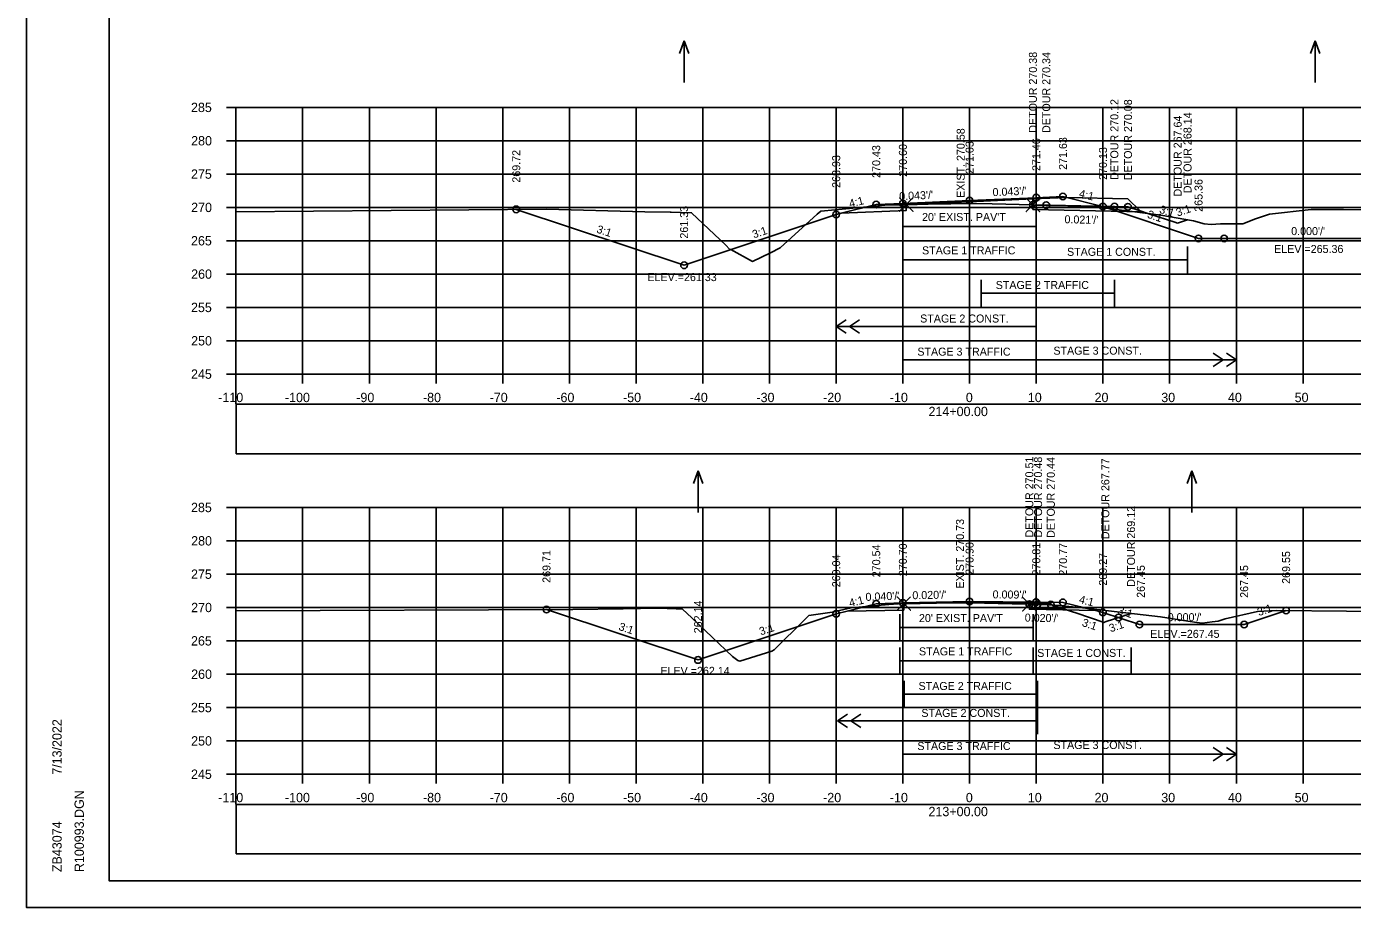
# Model space of a CAD drawing. Extents: x 4667 to 1632277, y -2100 to 724501.
# Drawn here: x 5635.8 to 5834.6, y -1750.4 to -1618.3 of the extents above; entities that cross this region are included whole.
import ezdxf

# ---------------------------------------------------------------- set-up
doc = ezdxf.new("R2010")
doc.units = 0
for name, color, linetype in [('R_Alt Surface', 7, 'Continuous'), ('R_Axis', 7, 'Continuous'), ('R_Axis Annot', 7, 'Continuous'), ('R_Border', 7, 'Continuous'), ('R_Detour', 7, 'Continuous'), ('R_Detour Annot', 7, 'Continuous'), ('R_Exist Surface', 7, 'Continuous'), ('R_Fin Surface', 7, 'Continuous'), ('R_Fin Surface Annot', 7, 'Continuous'), ('R_Grid', 7, 'Continuous'), ('R_No Plot', 7, 'Continuous'), ('R_Proposed CofA', 7, 'Continuous'), ('R_Temp Easement', 7, 'Continuous'), ('R_Water Annot', 7, 'Continuous'), ('T_Notes', 7, 'Continuous')]:
    doc.layers.add(name, color=color, linetype=linetype)

msp = doc.modelspace()

# ---------------------------------------------------------------- linework, layer by layer
at = {"layer": 'R_Alt Surface'}
for points in [[(5757.95, -1646.32), (5767.69, -1645.9), (5767.69, -1644.99), (5777.18, -1644.58), (5786.68, -1644.17), (5786.68, -1645.09), (5797.13, -1645.3)], [(5758.82, -1705.99), (5767.32, -1705.82), (5767.32, -1704.91), (5777.18, -1704.71), (5786.14, -1704.79), (5786.14, -1705.71), (5796.13, -1705.91)]]:
    msp.add_lwpolyline(points, dxfattribs=at)
at = {"layer": 'R_Axis'}
for p, q in [((5665.78, -1630.44), (5667.18, -1630.44)), ((5667.18, -1670.44), (5667.18, -1630.44)), ((5665.78, -1635.44), (5667.18, -1635.44)), ((5665.78, -1640.44), (5667.18, -1640.44)), ((5665.78, -1645.44), (5667.18, -1645.44)), ((5665.78, -1650.44), (5667.18, -1650.44)), ((5665.78, -1655.44), (5667.18, -1655.44)), ((5665.78, -1660.44), (5667.18, -1660.44)), ((5665.78, -1665.44), (5667.18, -1665.44)), ((5665.78, -1670.44), (5667.18, -1670.44)), ((5667.18, -1670.44), (5947.18, -1670.44)), ((5667.18, -1671.84), (5667.18, -1670.44)), ((5677.18, -1671.84), (5677.18, -1670.44)), ((5687.18, -1671.84), (5687.18, -1670.44)), ((5697.18, -1671.84), (5697.18, -1670.44)), ((5707.18, -1671.84), (5707.18, -1670.44)), ((5717.18, -1671.84), (5717.18, -1670.44)), ((5727.18, -1671.84), (5727.18, -1670.44)), ((5737.18, -1671.84), (5737.18, -1670.44)), ((5747.18, -1671.84), (5747.18, -1670.44)), ((5757.18, -1671.84), (5757.18, -1670.44)), ((5767.18, -1671.84), (5767.18, -1670.44)), ((5777.18, -1671.84), (5777.18, -1670.44)), ((5787.18, -1671.84), (5787.18, -1670.44)), ((5797.18, -1671.84), (5797.18, -1670.44)), ((5807.18, -1671.84), (5807.18, -1670.44)), ((5817.18, -1671.84), (5817.18, -1670.44)), ((5827.18, -1671.84), (5827.18, -1670.44)), ((5665.78, -1690.44), (5667.18, -1690.44)), ((5667.18, -1730.44), (5667.18, -1690.44)), ((5665.78, -1695.44), (5667.18, -1695.44)), ((5665.78, -1700.44), (5667.18, -1700.44)), ((5665.78, -1705.44), (5667.18, -1705.44)), ((5665.78, -1710.44), (5667.18, -1710.44)), ((5665.78, -1715.44), (5667.18, -1715.44)), ((5665.78, -1720.44), (5667.18, -1720.44)), ((5665.78, -1725.44), (5667.18, -1725.44)), ((5665.78, -1730.44), (5667.18, -1730.44)), ((5667.18, -1730.44), (5947.18, -1730.44)), ((5667.18, -1731.84), (5667.18, -1730.44)), ((5677.18, -1731.84), (5677.18, -1730.44)), ((5687.18, -1731.84), (5687.18, -1730.44)), ((5697.18, -1731.84), (5697.18, -1730.44)), ((5707.18, -1731.84), (5707.18, -1730.44)), ((5717.18, -1731.84), (5717.18, -1730.44)), ((5727.18, -1731.84), (5727.18, -1730.44)), ((5737.18, -1731.84), (5737.18, -1730.44)), ((5747.18, -1731.84), (5747.18, -1730.44)), ((5757.18, -1731.84), (5757.18, -1730.44)), ((5767.18, -1731.84), (5767.18, -1730.44)), ((5777.18, -1731.84), (5777.18, -1730.44)), ((5787.18, -1731.84), (5787.18, -1730.44)), ((5797.18, -1731.84), (5797.18, -1730.44)), ((5807.18, -1731.84), (5807.18, -1730.44)), ((5817.18, -1731.84), (5817.18, -1730.44)), ((5827.18, -1731.84), (5827.18, -1730.44))]:
    msp.add_line(p, q, dxfattribs=at)
at = {"layer": 'R_Border'}
for p, q in [((5648.18, -1746.44), (5648.18, -1540.98)), ((5648.18, -1746.44), (5648.18, -1746.44)), ((5964.36, -1746.44), (5648.18, -1746.44))]:
    msp.add_line(p, q, dxfattribs=at)
at = {"layer": 'R_Detour'}
msp.add_line((5808.38, -1647.8), (5809.86, -1647.31), dxfattribs=at)
for points in [[(5786.68, -1645.73), (5786.68, -1645.06)], [(5786.68, -1645.06), (5788.65, -1645.1), (5788.68, -1645.1), (5788.87, -1645.11), (5789.32, -1645.12), (5796.12, -1645.26), (5798.89, -1645.32), (5799.76, -1645.34), (5800.93, -1645.36), (5802.45, -1645.86), (5804.19, -1646.43), (5807.98, -1647.67), (5808.38, -1647.8)], [(5803.1, -1646.08), (5786.68, -1645.73)], [(5786.14, -1704.94), (5787.22, -1704.96), (5787.36, -1704.96), (5787.62, -1704.97), (5789.36, -1705), (5789.75, -1705.13), (5792.63, -1706.09), (5793.11, -1706.25), (5797.37, -1707.67), (5797.53, -1707.61), (5801.39, -1706.33)], [(5786.15, -1705.6), (5786.14, -1704.94)], [(5791.49, -1705.71), (5786.15, -1705.6)]]:
    msp.add_lwpolyline(points, dxfattribs=at)
at = {"layer": 'R_Exist Surface'}
for points in [[(5667.18, -1646.1), (5713.72, -1645.69), (5728.51, -1646.09), (5732.27, -1646.13), (5732.44, -1646.13), (5735.5, -1646.23), (5740.61, -1651.09), (5741.17, -1651.69), (5741.36, -1651.74), (5744.64, -1653.53), (5747.34, -1652.25), (5748.78, -1651.5), (5754.33, -1646.47), (5754.87, -1645.99), (5757.04, -1645.78), (5765.04, -1645.06), (5766.84, -1645.03), (5767.28, -1645.03), (5767.69, -1645.01), (5767.7, -1645.03), (5770.97, -1644.97), (5777.79, -1644.86), (5780.58, -1644.92), (5786.68, -1645.06), (5788.66, -1645.13), (5789.49, -1645.15), (5792.26, -1645.21), (5796.44, -1645.39), (5805.86, -1646.61), (5810.74, -1647.46), (5812.36, -1647.9), (5813.38, -1647.99), (5814.79, -1647.9), (5818.15, -1647.92), (5820.05, -1647.17), (5822.16, -1646.44), (5828.38, -1645.73), (5833.23, -1645.74), (5844.62, -1645.81)], [(5667.18, -1705.96), (5717.67, -1705.72), (5725.26, -1705.64), (5730.48, -1705.55), (5733.17, -1705.65), (5734.12, -1705.7), (5735.54, -1707.01), (5741.62, -1712.77), (5742.41, -1713.37), (5742.72, -1713.51), (5747.51, -1711.97), (5747.89, -1711.79), (5752.48, -1707.22), (5753.09, -1706.62), (5756.56, -1706.16), (5759.45, -1705.5), (5765.07, -1705), (5766.51, -1704.88), (5767.32, -1704.84), (5770.37, -1704.8), (5777.32, -1704.72), (5783.56, -1704.89), (5786.14, -1704.94), (5786.93, -1704.99), (5788.36, -1705.01), (5790.58, -1705.16), (5794.13, -1705.5), (5805.8, -1706.83), (5809.9, -1707.48), (5811.26, -1707.7), (5812.06, -1707.8), (5813.57, -1707.61), (5814.44, -1707.5), (5815.5, -1707.15), (5820.34, -1706.05), (5823.27, -1705.88), (5833.72, -1705.98), (5838.88, -1706.04)]]:
    msp.add_lwpolyline(points, dxfattribs=at)
at = {"layer": 'R_Fin Surface'}
for points in [[(5709.21, -1645.73), (5734.37, -1654.12), (5757.18, -1646.51), (5757.95, -1646.32), (5763.18, -1645.01), (5767.18, -1644.84), (5777.18, -1644.41), (5787.18, -1643.98), (5791.18, -1643.81), (5797.13, -1645.3), (5797.18, -1645.31), (5811.51, -1650.09), (5846.51, -1650.09), (5858.5, -1646.09)], [(5713.74, -1705.74), (5736.46, -1713.31), (5757.18, -1706.4), (5758.82, -1705.99), (5763.18, -1704.9), (5767.18, -1704.74), (5777.18, -1704.54), (5787.18, -1704.64), (5791.18, -1704.67), (5796.13, -1705.91), (5797.18, -1706.17), (5802.64, -1707.99), (5818.35, -1707.99), (5824.64, -1705.89)]]:
    msp.add_lwpolyline(points, dxfattribs=at)
at = {"layer": 'R_Grid'}
for p, q in [((5667.18, -1630.44), (5947.18, -1630.44)), ((5667.18, -1670.44), (5667.18, -1630.44)), ((5677.18, -1670.44), (5677.18, -1630.44)), ((5687.18, -1670.44), (5687.18, -1630.44)), ((5697.18, -1670.44), (5697.18, -1630.44)), ((5707.18, -1670.44), (5707.18, -1630.44)), ((5717.18, -1670.44), (5717.18, -1630.44)), ((5727.18, -1670.44), (5727.18, -1630.44)), ((5737.18, -1670.44), (5737.18, -1630.44)), ((5747.18, -1670.44), (5747.18, -1630.44)), ((5757.18, -1670.44), (5757.18, -1630.44)), ((5767.18, -1670.44), (5767.18, -1630.44)), ((5777.18, -1670.44), (5777.18, -1630.44)), ((5787.18, -1670.44), (5787.18, -1630.44)), ((5797.18, -1670.44), (5797.18, -1630.44)), ((5807.18, -1670.44), (5807.18, -1630.44)), ((5817.18, -1670.44), (5817.18, -1630.44)), ((5827.18, -1670.44), (5827.18, -1630.44)), ((5667.18, -1635.44), (5947.18, -1635.44)), ((5667.18, -1640.44), (5947.18, -1640.44)), ((5667.18, -1645.44), (5947.18, -1645.44)), ((5667.18, -1650.44), (5947.18, -1650.44)), ((5667.18, -1655.44), (5947.18, -1655.44)), ((5667.18, -1660.44), (5947.18, -1660.44)), ((5667.18, -1665.44), (5947.18, -1665.44)), ((5667.18, -1670.44), (5947.18, -1670.44)), ((5667.18, -1690.44), (5947.18, -1690.44)), ((5667.18, -1730.44), (5667.18, -1690.44)), ((5677.18, -1730.44), (5677.18, -1690.44)), ((5687.18, -1730.44), (5687.18, -1690.44)), ((5697.18, -1730.44), (5697.18, -1690.44)), ((5707.18, -1730.44), (5707.18, -1690.44)), ((5717.18, -1730.44), (5717.18, -1690.44)), ((5727.18, -1730.44), (5727.18, -1690.44)), ((5737.18, -1730.44), (5737.18, -1690.44)), ((5747.18, -1730.44), (5747.18, -1690.44)), ((5757.18, -1730.44), (5757.18, -1690.44)), ((5767.18, -1730.44), (5767.18, -1690.44)), ((5777.18, -1730.44), (5777.18, -1690.44)), ((5787.18, -1730.44), (5787.18, -1690.44)), ((5797.18, -1730.44), (5797.18, -1690.44)), ((5807.18, -1730.44), (5807.18, -1690.44)), ((5817.18, -1730.44), (5817.18, -1690.44)), ((5827.18, -1730.44), (5827.18, -1690.44)), ((5667.18, -1695.44), (5947.18, -1695.44)), ((5667.18, -1700.44), (5947.18, -1700.44)), ((5667.18, -1705.44), (5947.18, -1705.44)), ((5667.18, -1710.44), (5947.18, -1710.44)), ((5667.18, -1715.44), (5947.18, -1715.44)), ((5667.18, -1720.44), (5947.18, -1720.44)), ((5667.18, -1725.44), (5947.18, -1725.44)), ((5667.18, -1730.44), (5947.18, -1730.44))]:
    msp.add_line(p, q, dxfattribs=at)
at = {"layer": 'R_No Plot'}
for p, q in [((5667.18, -1671.84), (5667.18, -1674.92)), ((5667.18, -1731.84), (5667.18, -1734.92)), ((5635.78, -1750.42), (5969.12, -1750.42))]:
    msp.add_line(p, q, dxfattribs=at)
for points in [[(5635.78, -1537.09), (5969.12, -1537.09), (5969.12, -1750.43), (5635.78, -1750.43)], [(5882.1, -1540.98), (5901.72, -1540.98), (5901.72, -1550.86), (5917.84, -1550.86), (5941.04, -1550.86), (5941.04, -1575.2), (5964.36, -1575.2), (5964.36, -1746.44), (5648.18, -1746.44), (5648.18, -1540.98)]]:
    msp.add_lwpolyline(points, close=True, dxfattribs=at)
for points in [[(5767.69, -1645.01), (5766.69, -1644.01), (5767.69, -1645.01), (5766.69, -1646.01), (5767.69, -1645.01), (5768.69, -1646.01), (5767.69, -1645.01), (5768.69, -1644.01)], [(5786.68, -1645.06), (5785.68, -1644.06), (5786.68, -1645.06), (5785.68, -1646.06), (5786.68, -1645.06), (5787.68, -1646.06), (5786.68, -1645.06), (5787.68, -1644.06)], [(5767.32, -1704.84), (5766.32, -1703.84), (5767.32, -1704.84), (5766.32, -1705.84), (5767.32, -1704.84), (5768.32, -1705.84), (5767.32, -1704.84), (5768.32, -1703.84)], [(5786.14, -1704.94), (5785.14, -1703.94), (5786.14, -1704.94), (5785.14, -1705.94), (5786.14, -1704.94), (5787.14, -1705.94), (5786.14, -1704.94), (5787.14, -1703.94)]]:
    msp.add_lwpolyline(points, dxfattribs=at)
for centre in [(5777.18, -1644.41), (5787.18, -1643.98), (5791.18, -1643.81), (5709.21, -1645.73), (5757.18, -1646.51), (5763.18, -1645.01), (5767.18, -1644.84), (5786.68, -1645.06), (5788.68, -1645.1), (5797.18, -1645.31), (5798.89, -1645.32), (5800.93, -1645.36), (5811.51, -1650.09), (5815.34, -1650.09), (5734.37, -1654.12), (5713.74, -1705.74), (5763.18, -1704.9), (5767.18, -1704.74), (5777.18, -1704.54), (5786.14, -1704.94), (5787.18, -1704.64), (5787.36, -1704.96), (5789.36, -1705), (5791.18, -1704.67), (5797.18, -1706.17), (5824.64, -1705.89), (5757.18, -1706.4), (5799.52, -1706.95), (5802.64, -1707.99), (5818.35, -1707.99), (5736.46, -1713.31)]:
    msp.add_circle(centre, 0.5, dxfattribs=at)
at = {"layer": 'R_Proposed CofA'}
for p, q in [((5757.18, -1663.28), (5758.68, -1662.28)), ((5757.18, -1663.28), (5758.68, -1664.28)), ((5759.18, -1663.28), (5760.68, -1662.28)), ((5759.18, -1663.28), (5760.68, -1664.28)), ((5815.18, -1668.28), (5813.68, -1667.28)), ((5817.18, -1668.28), (5815.68, -1667.28)), ((5815.18, -1668.28), (5813.68, -1669.28)), ((5817.18, -1668.28), (5815.68, -1669.28)), ((5757.36, -1722.42), (5758.86, -1721.42)), ((5759.36, -1722.42), (5760.86, -1721.42)), ((5757.36, -1722.42), (5758.86, -1723.42)), ((5759.36, -1722.42), (5760.86, -1723.42)), ((5815.18, -1727.42), (5813.68, -1726.42)), ((5815.18, -1727.42), (5813.68, -1728.42)), ((5817.18, -1727.42), (5815.68, -1726.42)), ((5817.18, -1727.42), (5815.68, -1728.42))]:
    msp.add_line(p, q, dxfattribs=at)
for points in [[(5667.23, -1682.39), (5947.13, -1682.39), (5947.13, -1674.97), (5667.23, -1674.97)], [(5667.23, -1742.39), (5947.13, -1742.39), (5947.13, -1734.97), (5667.23, -1734.97)]]:
    msp.add_lwpolyline(points, close=True, dxfattribs=at)
at = {"layer": 'R_Temp Easement'}
for p, q in [((5767.18, -1650.28), (5767.18, -1646.28)), ((5787.18, -1650.28), (5787.18, -1646.28)), ((5767.18, -1648.28), (5787.18, -1648.28)), ((5767.18, -1655.28), (5767.18, -1651.28)), ((5787.18, -1655.28), (5787.18, -1651.28)), ((5809.86, -1655.28), (5809.86, -1651.28)), ((5767.18, -1653.28), (5787.18, -1653.28)), ((5809.86, -1653.28), (5787.18, -1653.28)), ((5778.93, -1660.28), (5778.93, -1656.28)), ((5798.93, -1660.28), (5798.93, -1656.28)), ((5798.93, -1658.28), (5778.93, -1658.28)), ((5787.18, -1665.28), (5787.18, -1661.28)), ((5787.18, -1663.28), (5757.18, -1663.28)), ((5767.18, -1670.28), (5767.18, -1666.28)), ((5787.18, -1670.28), (5787.18, -1666.28)), ((5787.18, -1668.28), (5767.18, -1668.28)), ((5787.18, -1668.28), (5817.18, -1668.28)), ((5766.73, -1710.42), (5766.73, -1706.42)), ((5786.73, -1710.42), (5786.73, -1706.42)), ((5766.73, -1708.42), (5786.73, -1708.42)), ((5766.73, -1715.42), (5766.73, -1711.42)), ((5786.73, -1715.42), (5786.73, -1711.42)), ((5801.39, -1715.42), (5801.39, -1711.42)), ((5766.73, -1713.42), (5786.73, -1713.42)), ((5801.39, -1713.42), (5786.73, -1713.42)), ((5767.36, -1720.42), (5767.36, -1716.42)), ((5787.36, -1720.42), (5787.36, -1716.42)), ((5787.36, -1718.42), (5767.36, -1718.42)), ((5787.36, -1724.42), (5787.36, -1720.42)), ((5787.36, -1722.42), (5757.36, -1722.42)), ((5767.18, -1729.42), (5767.18, -1725.42)), ((5787.18, -1729.42), (5787.18, -1725.42)), ((5787.18, -1727.42), (5767.18, -1727.42)), ((5787.18, -1727.42), (5817.18, -1727.42))]:
    msp.add_line(p, q, dxfattribs=at)
at = {"layer": 'R_Water Annot'}
for p, q in [((5734.37, -1620.44), (5733.67, -1622.37)), ((5734.37, -1626.73), (5734.37, -1620.44)), ((5734.37, -1620.44), (5735.07, -1622.37)), ((5829.01, -1620.44), (5828.31, -1622.37)), ((5829.01, -1626.73), (5829.01, -1620.44)), ((5829.01, -1620.44), (5829.71, -1622.37)), ((5736.46, -1684.92), (5735.76, -1686.84)), ((5736.46, -1691.2), (5736.46, -1684.92)), ((5736.46, -1684.92), (5737.16, -1686.84)), ((5810.49, -1684.92), (5809.79, -1686.84)), ((5810.49, -1691.2), (5810.49, -1684.92)), ((5810.49, -1684.92), (5811.19, -1686.84))]:
    msp.add_line(p, q, dxfattribs=at)
at = {"layer": 'T_Notes'}
for p, q in [((5791.75, -1643.95), (5800.93, -1644.14)), ((5800.93, -1644.14), (5802.76, -1645.96)), ((5802.76, -1645.96), (5800.93, -1645.36)), ((5789.36, -1704.82), (5789.63, -1705.09))]:
    msp.add_line(p, q, dxfattribs=at)
for points in [[(5767.69, -1644.99), (5786.68, -1644.17), (5791.75, -1643.95)], [(5800.93, -1645.36), (5786.68, -1645.06), (5780.58, -1644.92), (5777.79, -1644.86), (5770.97, -1644.97), (5767.7, -1645.03), (5767.69, -1645.01), (5767.69, -1644.99)], [(5776.19, -1704.73), (5777.18, -1704.71), (5786.14, -1704.79), (5789.36, -1704.82)], [(5789.63, -1705.09), (5789.36, -1705), (5786.14, -1704.94), (5783.56, -1704.89), (5777.32, -1704.72), (5776.19, -1704.73)]]:
    msp.add_lwpolyline(points, dxfattribs=at)

# ---------------------------------------------------------------- texts
at = {"layer": 'R_Axis Annot'}
for s, p in [('285', (5660.44, -1631.14)), ('280', (5660.46, -1636.14)), ('275', (5660.44, -1641.14)), ('270', (5660.46, -1646.14)), ('265', (5660.44, -1651.14)), ('260', (5660.46, -1656.14)), ('255', (5660.44, -1661.14)), ('250', (5660.46, -1666.14)), ('245', (5660.44, -1671.14)), ('-110', (5664.52, -1674.64)), ('-100', (5674.52, -1674.64)), ('-90', (5685.22, -1674.64)), ('-80', (5695.22, -1674.64)), ('-70', (5705.22, -1674.64)), ('-60', (5715.22, -1674.64)), ('-50', (5725.22, -1674.64)), ('-40', (5735.22, -1674.64)), ('-30', (5745.22, -1674.64)), ('-20', (5755.22, -1674.64)), ('-10', (5765.22, -1674.64)), ('0', (5776.62, -1674.64)), ('10', (5785.92, -1674.64)), ('20', (5795.92, -1674.64)), ('30', (5805.92, -1674.64)), ('40', (5815.92, -1674.64)), ('50', (5825.92, -1674.64)), ('214+00.00', (5771.02, -1676.74)), ('285', (5660.44, -1691.14)), ('280', (5660.46, -1696.14)), ('275', (5660.44, -1701.14)), ('270', (5660.46, -1706.14)), ('265', (5660.44, -1711.14)), ('260', (5660.46, -1716.14)), ('255', (5660.44, -1721.14)), ('250', (5660.46, -1726.14)), ('245', (5660.44, -1731.14)), ('-110', (5664.52, -1734.64)), ('-100', (5674.52, -1734.64)), ('-90', (5685.22, -1734.64)), ('-80', (5695.22, -1734.64)), ('-70', (5705.22, -1734.64)), ('-60', (5715.22, -1734.64)), ('-50', (5725.22, -1734.64)), ('-40', (5735.22, -1734.64)), ('-30', (5745.22, -1734.64)), ('-20', (5755.22, -1734.64)), ('-10', (5765.22, -1734.64)), ('0', (5776.62, -1734.64)), ('10', (5785.92, -1734.64)), ('20', (5795.92, -1734.64)), ('30', (5805.92, -1734.64)), ('40', (5815.92, -1734.64)), ('50', (5825.92, -1734.64)), ('213+00.00', (5771.02, -1736.74))]:
    msp.add_text(s, height=1.4, dxfattribs=at).set_placement(p)
at = {"layer": 'R_Border'}
for s, p in [('7/13/2022', (5641.05, -1730.52)), ('R100993.DGN', (5644.38, -1745.12)), ('ZB43074', (5641.05, -1745.12))]:
    msp.add_text(s, height=1.4, rotation=90, dxfattribs=at).set_placement(p)
at = {"layer": 'R_Detour Annot'}
for s, rotation, p in [('3:1', 341.8473, (5805.55, -1646.22)), ('3:1', 18.4389, (5808.37, -1646.82)), ("0.021'/'", 358.7911, (5791.4, -1647.81)), ('DETOUR 267.77', 90, (5798.13, -1695.2)), ("0.020'/'", 358.854, (5785.44, -1707.55)), ('3:1', 341.8473, (5793.94, -1708.19)), ('3:1', 18.6993, (5798.33, -1709.17))]:
    msp.add_text(s, height=1.2, rotation=rotation, dxfattribs=at).set_placement(p)
at = {"layer": 'R_Fin Surface Annot'}
for s, rotation, p in [('DETOUR 270.38', 90, (5787.28, -1634.24)), ('DETOUR 270.34', 90, (5789.28, -1634.28)), ('DETOUR 270.12', 90, (5799.49, -1641.32)), ('DETOUR 270.08', 90, (5801.53, -1641.36)), ('DETOUR 267.64', 90, (5808.98, -1643.8)), ('DETOUR 268.14', 90, (5810.46, -1643.31)), ('270.43', 90, (5763.78, -1641.01)), ('270.60', 90, (5767.78, -1640.84)), ('271.03', 90, (5777.78, -1640.41)), ('271.46', 90, (5787.78, -1639.98)), ('271.63', 90, (5791.78, -1639.81)), ('269.72', 90, (5709.81, -1641.73)), ('268.93', 90, (5757.78, -1642.51)), ('270.13', 90, (5797.78, -1641.31)), ('265.36', 90, (5812.11, -1646.09)), ('4:1', 14.0362, (5759.26, -1645.48)), ("0.043'/'", 2.4566, (5766.65, -1644.36)), ("0.043'/'", 2.4566, (5780.65, -1643.76)), ('4:1', 345.9638, (5793.5, -1643.88)), ('261.33', 90, (5734.97, -1650.12)), ('3:1', 341.5651, (5803.72, -1646.96)), ('3:1', 341.5651, (5721.16, -1649.19)), ('3:1', 18.4349, (5744.83, -1650.1)), ("0.000'/'", 360, (5825.4, -1649.59)), ('DETOUR 270.51', 90, (5786.74, -1694.94)), ('DETOUR 270.48', 90, (5788.05, -1694.96)), ('DETOUR 270.44', 90, (5789.96, -1695)), ('DETOUR 269.12', 90, (5801.99, -1702.33)), ('270.70', 90, (5767.78, -1700.74)), ('270.90', 90, (5777.78, -1700.54)), ('270.81', 90, (5787.78, -1700.64)), ('270.77', 90, (5791.78, -1700.67)), ('269.71', 90, (5714.34, -1701.74)), ('269.04', 90, (5757.78, -1702.4)), ('270.54', 90, (5763.78, -1700.9)), ('269.27', 90, (5797.78, -1702.17)), ('269.55', 90, (5825.24, -1701.89)), ('267.45', 90, (5803.46, -1703.99)), ('267.45', 90, (5818.95, -1703.99)), ('4:1', 14.0362, (5759.26, -1705.37)), ("0.040'/'", 2.2906, (5761.6, -1704.46)), ("0.020'/'", 1.1458, (5768.61, -1704.21)), ("0.009'/'", 359.4616, (5780.63, -1704.07)), ('4:1', 345.9638, (5793.5, -1704.74)), ('262.14', 90, (5737.06, -1709.31)), ('3:1', 341.5651, (5799.28, -1706.34)), ('3:1', 18.4349, (5820.55, -1706.73)), ('3:1', 341.5651, (5724.47, -1708.78)), ("0.000'/'", 360, (5806.89, -1707.49)), ('3:1', 18.4349, (5745.88, -1709.64))]:
    msp.add_text(s, height=1.2, rotation=rotation, dxfattribs=at).set_placement(p)
at = {"layer": 'R_Temp Easement'}
for s, p in [('EXIST. 270.58', (5776.45, -1644.01)), ('EXIST. 270.73', (5776.34, -1702.6))]:
    msp.add_text(s, height=1.2, rotation=90, dxfattribs=at).set_placement(p)
for s, height, p in [("20' EXIST. PAV'T", 1.2, (5770.05, -1647.48)), ('STAGE 1 TRAFFIC', 1.2, (5770.05, -1652.48)), ('STAGE 1 CONST.', 1.1985, (5791.79, -1652.7)), ('STAGE 2 TRAFFIC', 1.1985, (5781.1, -1657.67)), ('STAGE 2 CONST.', 1.1985, (5769.77, -1662.7)), ('STAGE 3 TRAFFIC', 1.1985, (5769.35, -1667.67)), ('STAGE 3 CONST.', 1.1985, (5789.75, -1667.52)), ("20' EXIST. PAV'T", 1.2, (5769.59, -1707.62)), ('STAGE 1 TRAFFIC', 1.2, (5769.59, -1712.62)), ('STAGE 1 CONST.', 1.1985, (5787.32, -1712.85)), ('STAGE 2 TRAFFIC', 1.1985, (5769.53, -1717.81)), ('STAGE 2 CONST.', 1.1985, (5769.95, -1721.85)), ('STAGE 3 TRAFFIC', 1.1985, (5769.35, -1726.81)), ('STAGE 3 CONST.', 1.1985, (5789.75, -1726.66))]:
    msp.add_text(s, height=height, dxfattribs=at).set_placement(p)
at = {"layer": 'R_Water Annot'}
for s, p in [('ELEV.=265.36', (5822.84, -1652.27)), ('ELEV.=261.33', (5728.87, -1656.49)), ('ELEV.=267.45', (5804.27, -1709.99)), ('ELEV.=262.14', (5730.82, -1715.54))]:
    msp.add_text(s, height=1.2, dxfattribs=at).set_placement(p)

doc.saveas('drawing.dxf')
